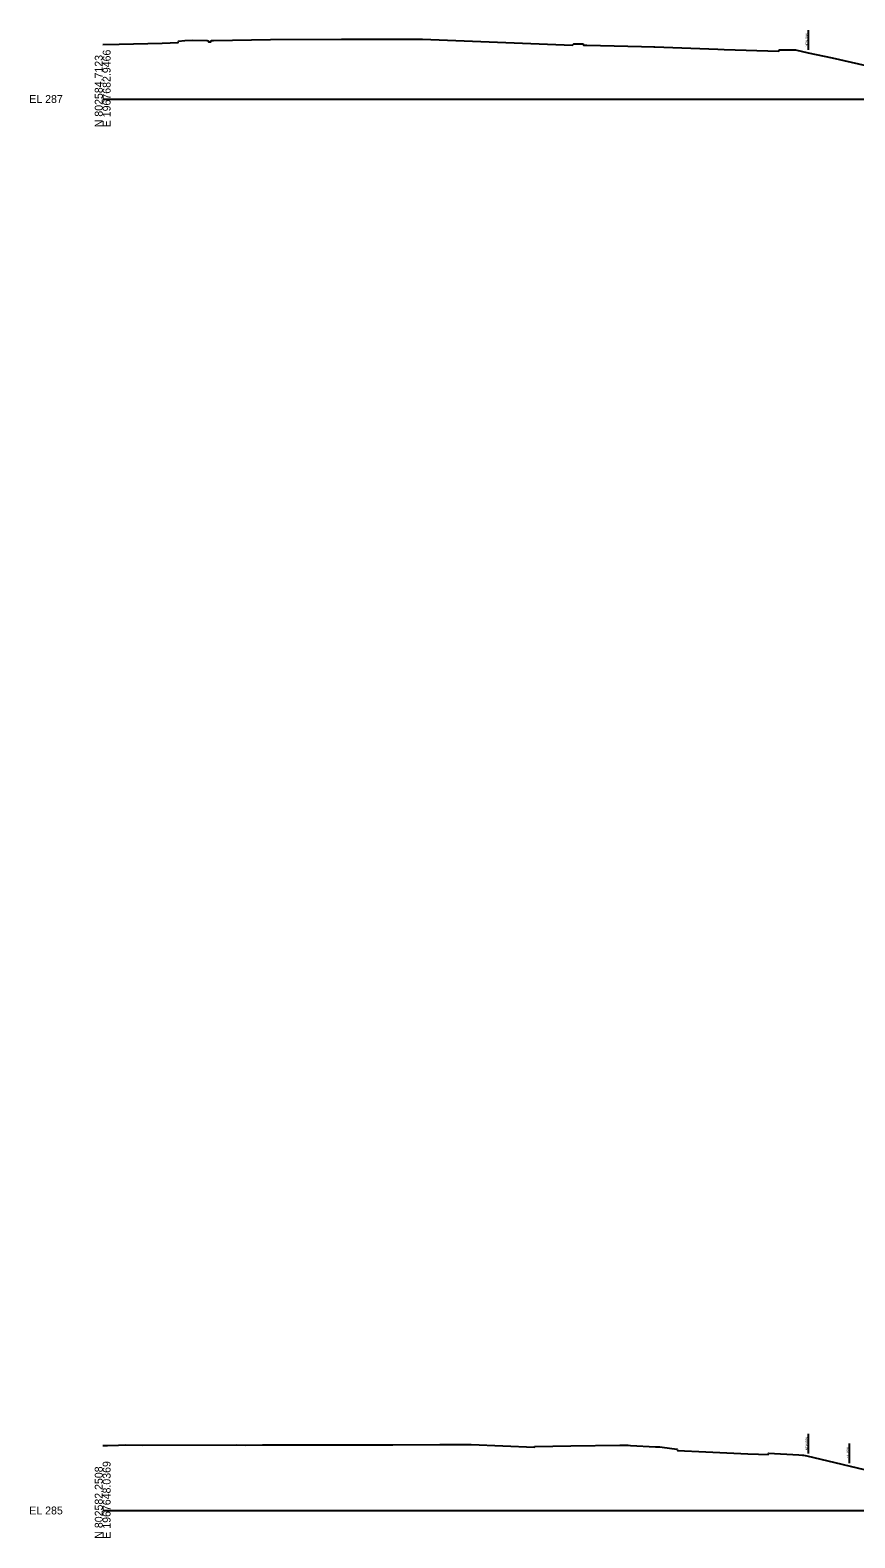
# Model space of a CAD drawing. Extents: x -26 to 1986619, y -10 to 827846.
# Drawn here: x -26 to 266, y 28490 to 29024 of the extents above; entities that cross this region are included whole.
import ezdxf

# ---------------------------------------------------------------- set-up
doc = ezdxf.new("R2010")
doc.units = 0
for name, color, linetype in [('Default', 7, 'Continuous'), ('RD_GPK_XS_Cell', 7, 'Continuous'), ('RD_XS_ExGround', 7, 'Continuous'), ('RD_XS_ExRW', 7, 'Continuous'), ('RD_XS_NewRW', 7, 'Continuous')]:
    doc.layers.add(name, color=color, linetype=linetype)

msp = doc.modelspace()

# ---------------------------------------------------------------- linework, layer by layer
at = {"layer": 'RD_GPK_XS_Cell'}
for p, q in [((0, 29000), (300, 29000)), ((0, 28500), (300, 28500))]:
    msp.add_line(p, q, dxfattribs=at)
at = {"layer": 'RD_XS_ExGround'}
for points in [[(0, 29019.31), (5.88, 29019.46), (21.09, 29019.8), (26.72, 29019.99), (26.84, 29020.44), (29.07, 29020.7), (31.8, 29020.87), (36.98, 29020.68), (37.37, 29020.65), (37.49, 29020.21), (38.34, 29020.23), (38.52, 29020.68), (39.31, 29020.69), (59.42, 29021.13), (84.56, 29021.17), (88.53, 29021.18), (113.3, 29021.21), (166.47, 29019.12), (166.89, 29019.54), (167.59, 29019.55), (168.5, 29019.56), (169.36, 29019.55), (170.16, 29019.49), (170.3, 29019.04), (171.54, 29019.05), (190.82, 29018.58), (195.21, 29018.47), (195.54, 29018.45), (217.92, 29017.63), (220.11, 29017.56), (239.49, 29016.97), (239.61, 29017.42), (240.23, 29017.42), (241.2, 29017.42), (245.46, 29017.43), (249.94, 29016.41), (258.46, 29014.53), (274.45, 29010.94)], [(0, 28523.04), (1.66, 28523.07), (5.66, 28523.15), (8.08, 28523.21), (14.17, 28523.17), (47.29, 28523.26), (50.45, 28523.12), (56.61, 28523.24), (78.17, 28523.25), (86.67, 28523.27), (102.74, 28523.3), (119.46, 28523.32), (130.5, 28523.34), (152.95, 28522.48), (153.12, 28522.65), (165.87, 28522.89), (183.15, 28523.13), (185.67, 28523.1), (186.16, 28523.09), (187.01, 28523.05), (195.8, 28522.59), (197.33, 28522.59), (201.64, 28521.97), (203.49, 28521.67), (203.59, 28521.22), (213.61, 28520.82), (226.07, 28520.23), (228.48, 28520.12), (232.3, 28519.96), (235.79, 28519.89), (235.89, 28520.34), (246.61, 28519.71), (247.86, 28519.64), (248.2, 28519.63), (249.4, 28519.35), (300, 28507.35)]]:
    msp.add_lwpolyline(points, dxfattribs=at)
at = {"layer": 'RD_XS_ExRW'}
msp.add_line((264.5, 28516.77), (264.5, 28523.77), dxfattribs=at)
at = {"layer": 'RD_XS_NewRW'}
for p, q in [((250, 29017.39), (250, 29024.39)), ((250, 28520.21), (250, 28527.21))]:
    msp.add_line(p, q, dxfattribs=at)

# ---------------------------------------------------------------- texts
at = {"layer": 'Default'}
for p in [(0, 29000), (0, 28500)]:
    msp.add_text('-', height=0.0001, dxfattribs=at).set_placement(p)
at = {"layer": 'RD_GPK_XS_Cell'}
for s, p in [('E 1967682.9466', (2.8, 28990)), ('N 802584.7123', (0, 28990)), ('N 802582.2508', (0, 28490)), ('E 1967648.0369', (2.8, 28490))]:
    msp.add_text(s, height=2.8, rotation=90, dxfattribs=at).set_placement(p)
for s, p in [('EL 287', (-26, 28998.6)), ('EL 285', (-26, 28498.6))]:
    msp.add_text(s, height=2.8, dxfattribs=at).set_placement(p)
at = {"layer": 'RD_XS_ExRW'}
msp.add_text('EX. R/W ', height=0.75, rotation=90, dxfattribs=at).set_placement((264.24, 28518.45))
at = {"layer": 'RD_XS_NewRW'}
for p in [(249.75, 29018.54), (249.75, 28521.36)]:
    msp.add_text('NEW R/W ', height=0.75, rotation=90, dxfattribs=at).set_placement(p)

doc.saveas('drawing.dxf')
